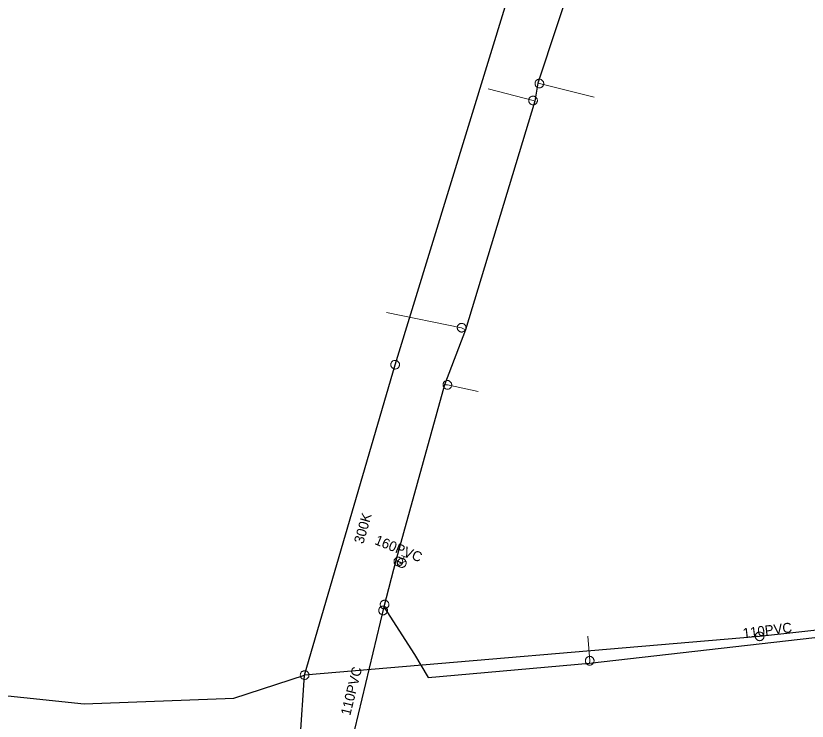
# Model space of a CAD drawing. Extents: x -741806 to -738704, y -1059275 to -1055387.
# Drawn here: x -740539.1 to -740459.3, y -1057576.9 to -1057505.9 of the extents above; entities that cross this region are included whole.
import ezdxf

# ---------------------------------------------------------------- set-up
doc = ezdxf.new("R2010")
doc.units = 0
doc.header["$LTSCALE"] = 0.4
for name, color, linetype, lineweight in [('2', 7, 'Continuous', 25), ('21', 7, 'Continuous', 13), ('3', 7, 'Continuous', 13), ('50', 7, 'Continuous', 13), ('51', 7, 'Continuous', 13), ('52', 7, 'Continuous', 25)]:
    doc.layers.add(name, color=color, linetype=linetype, lineweight=lineweight)
doc.layers.add('5', color=7, linetype='Continuous')
doc.layers.add('53', color=7, linetype='Continuous')

msp = doc.modelspace()

# ---------------------------------------------------------------- linework, layer by layer
at = {"layer": '2'}
msp.add_line((-740510.965, -1057587.065), (-740509.967, -1057572.304), dxfattribs=at)
for points in [[(-740509.967, -1057572.304), (-740500.848, -1057541.021), (-740485.947, -1057492.468), (-740470.69, -1057443.092), (-740463.206, -1057418.767)], [(-740283.166, -1057549.12), (-740314.092, -1057552.159), (-740363.478, -1057557.404), (-740409.581, -1057562.408), (-740464.129, -1057568.401), (-740509.967, -1057572.304)], [(-740633.142, -1057565.869), (-740616.157, -1057567.624), (-740600.686, -1057569.098), (-740568.695, -1057571.365), (-740532.184, -1057575.2), (-740517.113, -1057574.642), (-740509.967, -1057572.304)]]:
    msp.add_lwpolyline(points, dxfattribs=at)
at = {"layer": '21'}
for points in [[(-740486.488, -1057512.648), (-740486.32, -1057512.685), (-740480.791, -1057514.071)], [(-740486.78, -1057514.456), (-740486.956, -1057514.396), (-740491.467, -1057513.21)], [(-740493.754, -1057537.497), (-740494.153, -1057537.29), (-740501.713, -1057535.767)], [(-740495.864, -1057543.049), (-740495.588, -1057543.054), (-740492.478, -1057543.732)], [(-740481.265, -1057571.105), (-740481.25, -1057570.86), (-740481.438, -1057568.395)]]:
    msp.add_lwpolyline(points, dxfattribs=at)
at = {"layer": '3'}
for points in [[(-740500.724, -1057540.6), (-740500.769, -1057540.59), (-740500.814, -1057540.585), (-740500.86, -1057540.583), (-740500.905, -1057540.587), (-740500.95, -1057540.596), (-740500.995, -1057540.609), (-740501.036, -1057540.627), (-740501.077, -1057540.648), (-740501.114, -1057540.675), (-740501.149, -1057540.705), (-740501.18, -1057540.738), (-740501.209, -1057540.775), (-740501.231, -1057540.814), (-740501.252, -1057540.855), (-740501.267, -1057540.898), (-740501.278, -1057540.943), (-740501.282, -1057540.989), (-740501.284, -1057541.034), (-740501.28, -1057541.08), (-740501.271, -1057541.125), (-740501.258, -1057541.169), (-740501.241, -1057541.21), (-740501.218, -1057541.251), (-740501.193, -1057541.289), (-740501.162, -1057541.324), (-740501.129, -1057541.354), (-740501.093, -1057541.382), (-740501.053, -1057541.406), (-740501.012, -1057541.426), (-740500.968, -1057541.44), (-740500.925, -1057541.451), (-740500.879, -1057541.457), (-740500.833, -1057541.458), (-740500.787, -1057541.454), (-740500.743, -1057541.446), (-740500.698, -1057541.433), (-740500.657, -1057541.415), (-740500.616, -1057541.392), (-740500.579, -1057541.366), (-740500.544, -1057541.337), (-740500.513, -1057541.303), (-740500.484, -1057541.267), (-740500.461, -1057541.228), (-740500.441, -1057541.187), (-740500.427, -1057541.143), (-740500.416, -1057541.098), (-740500.41, -1057541.053), (-740500.409, -1057541.008), (-740500.413, -1057540.962), (-740500.422, -1057540.916), (-740500.435, -1057540.873), (-740500.452, -1057540.831), (-740500.475, -1057540.791), (-740500.5, -1057540.753), (-740500.531, -1057540.718), (-740500.564, -1057540.686), (-740500.6, -1057540.659), (-740500.64, -1057540.635), (-740500.681, -1057540.616)], [(-740509.843, -1057571.883), (-740509.888, -1057571.873), (-740509.933, -1057571.868), (-740509.979, -1057571.866), (-740510.024, -1057571.87), (-740510.069, -1057571.879), (-740510.114, -1057571.892), (-740510.155, -1057571.91), (-740510.196, -1057571.931), (-740510.233, -1057571.958), (-740510.268, -1057571.988), (-740510.299, -1057572.021), (-740510.328, -1057572.058), (-740510.35, -1057572.097), (-740510.371, -1057572.138), (-740510.386, -1057572.181), (-740510.397, -1057572.226), (-740510.401, -1057572.272), (-740510.403, -1057572.317), (-740510.399, -1057572.363), (-740510.39, -1057572.408), (-740510.377, -1057572.452), (-740510.36, -1057572.493), (-740510.337, -1057572.534), (-740510.312, -1057572.572), (-740510.281, -1057572.607), (-740510.248, -1057572.637), (-740510.212, -1057572.665), (-740510.172, -1057572.689), (-740510.131, -1057572.709), (-740510.087, -1057572.723), (-740510.044, -1057572.734), (-740509.998, -1057572.74), (-740509.952, -1057572.741), (-740509.906, -1057572.737), (-740509.862, -1057572.729), (-740509.817, -1057572.716), (-740509.776, -1057572.698), (-740509.735, -1057572.675), (-740509.698, -1057572.649), (-740509.663, -1057572.62), (-740509.632, -1057572.586), (-740509.603, -1057572.55), (-740509.58, -1057572.511), (-740509.56, -1057572.47), (-740509.546, -1057572.426), (-740509.535, -1057572.381), (-740509.529, -1057572.336), (-740509.528, -1057572.291), (-740509.532, -1057572.245), (-740509.541, -1057572.199), (-740509.554, -1057572.156), (-740509.571, -1057572.114), (-740509.594, -1057572.074), (-740509.619, -1057572.036), (-740509.65, -1057572.001), (-740509.683, -1057571.969), (-740509.719, -1057571.942), (-740509.759, -1057571.918), (-740509.8, -1057571.899)]]:
    msp.add_lwpolyline(points, close=True, dxfattribs=at)
msp.add_lwpolyline([(-740464.564, -1057568.448), (-740464.556, -1057568.492), (-740464.544, -1057568.536), (-740464.527, -1057568.58), (-740464.507, -1057568.62), (-740464.481, -1057568.658), (-740464.452, -1057568.694), (-740464.42, -1057568.726), (-740464.384, -1057568.755), (-740464.345, -1057568.779), (-740464.305, -1057568.8), (-740464.262, -1057568.816), (-740464.217, -1057568.828), (-740464.172, -1057568.834), (-740464.127, -1057568.837), (-740464.081, -1057568.834), (-740464.035, -1057568.827), (-740463.991, -1057568.815), (-740463.949, -1057568.799), (-740463.908, -1057568.777), (-740463.87, -1057568.752), (-740463.835, -1057568.723), (-740463.803, -1057568.691), (-740463.774, -1057568.655), (-740463.749, -1057568.617), (-740463.728, -1057568.575), (-740463.713, -1057568.532), (-740463.7, -1057568.489), (-740463.693, -1057568.443), (-740463.691, -1057568.397), (-740463.694, -1057568.351), (-740463.701, -1057568.307), (-740463.713, -1057568.263), (-740463.73, -1057568.219), (-740463.751, -1057568.178), (-740463.776, -1057568.141), (-740463.805, -1057568.105), (-740463.837, -1057568.073), (-740463.874, -1057568.044), (-740463.912, -1057568.02), (-740463.952, -1057567.999), (-740463.995, -1057567.983), (-740464.04, -1057567.971), (-740464.085, -1057567.964), (-740464.13, -1057567.962), (-740464.176, -1057567.965), (-740464.222, -1057567.972), (-740464.266, -1057567.984), (-740464.308, -1057568), (-740464.349, -1057568.022), (-740464.388, -1057568.047), (-740464.423, -1057568.076), (-740464.455, -1057568.108), (-740464.484, -1057568.144), (-740464.509, -1057568.182), (-740464.529, -1057568.224), (-740464.546, -1057568.267), (-740464.557, -1057568.31), (-740464.564, -1057568.356), (-740464.566, -1057568.402), (-740464.564, -1057568.447)], dxfattribs=at)
at = {"layer": '50'}
for p, q in [((-740500.211, -1057560.241), (-740499.925, -1057560.355)), ((-740500.018, -1057560.588), (-740499.925, -1057560.355)), ((-740499.64, -1057560.469), (-740499.925, -1057560.355)), ((-740500.183, -1057561.004), (-740500.595, -1057561.181)), ((-740500.183, -1057561.004), (-740499.775, -1057560.831))]:
    msp.add_line(p, q, dxfattribs=at)
msp.add_lwpolyline([(-740499.772, -1057561.172), (-740499.757, -1057561.125), (-740499.745, -1057561.081), (-740499.74, -1057561.033), (-740499.739, -1057560.987), (-740499.742, -1057560.943), (-740499.752, -1057560.895), (-740499.766, -1057560.852), (-740499.784, -1057560.807), (-740499.805, -1057560.766), (-740499.833, -1057560.729), (-740499.863, -1057560.693), (-740499.896, -1057560.66), (-740499.935, -1057560.633), (-740499.975, -1057560.609), (-740500.016, -1057560.589), (-740500.06, -1057560.575), (-740500.104, -1057560.563), (-740500.151, -1057560.558), (-740500.199, -1057560.557), (-740500.246, -1057560.561), (-740500.291, -1057560.57), (-740500.336, -1057560.583), (-740500.379, -1057560.601), (-740500.419, -1057560.623), (-740500.459, -1057560.65), (-740500.494, -1057560.68), (-740500.525, -1057560.714), (-740500.555, -1057560.752), (-740500.577, -1057560.793), (-740500.6, -1057560.833), (-740500.615, -1057560.879), (-740500.624, -1057560.924), (-740500.63, -1057560.968), (-740500.632, -1057561.017), (-740500.627, -1057561.063), (-740500.619, -1057561.109), (-740500.605, -1057561.153), (-740500.588, -1057561.197), (-740500.564, -1057561.239), (-740500.537, -1057561.276), (-740500.506, -1057561.312), (-740500.472, -1057561.343), (-740500.437, -1057561.372), (-740500.394, -1057561.397), (-740500.353, -1057561.417), (-740500.309, -1057561.432), (-740500.263, -1057561.441), (-740500.216, -1057561.448), (-740500.17, -1057561.449), (-740500.122, -1057561.445), (-740500.078, -1057561.436), (-740500.032, -1057561.423), (-740499.99, -1057561.405), (-740499.949, -1057561.383), (-740499.912, -1057561.354), (-740499.875, -1057561.326), (-740499.843, -1057561.291), (-740499.817, -1057561.253), (-740499.792, -1057561.214)], close=True, dxfattribs=at)
at = {"layer": '51'}
msp.add_lwpolyline([(-740485.893, -1057512.78), (-740485.885, -1057512.735), (-740485.882, -1057512.69), (-740485.884, -1057512.643), (-740485.891, -1057512.599), (-740485.902, -1057512.554), (-740485.918, -1057512.511), (-740485.939, -1057512.47), (-740485.963, -1057512.431), (-740485.992, -1057512.396), (-740486.024, -1057512.363), (-740486.06, -1057512.334), (-740486.098, -1057512.308), (-740486.138, -1057512.287), (-740486.181, -1057512.27), (-740486.225, -1057512.258), (-740486.27, -1057512.25), (-740486.316, -1057512.247), (-740486.361, -1057512.25), (-740486.407, -1057512.257), (-740486.452, -1057512.269), (-740486.494, -1057512.285), (-740486.535, -1057512.304), (-740486.574, -1057512.33), (-740486.61, -1057512.357), (-740486.642, -1057512.39), (-740486.672, -1057512.426), (-740486.697, -1057512.463), (-740486.718, -1057512.505), (-740486.735, -1057512.547), (-740486.747, -1057512.591), (-740486.754, -1057512.636), (-740486.757, -1057512.681), (-740486.755, -1057512.728), (-740486.749, -1057512.772), (-740486.737, -1057512.817), (-740486.721, -1057512.86), (-740486.7, -1057512.901), (-740486.676, -1057512.94), (-740486.647, -1057512.975), (-740486.615, -1057513.008), (-740486.58, -1057513.037), (-740486.542, -1057513.063), (-740486.501, -1057513.083), (-740486.459, -1057513.101), (-740486.414, -1057513.113), (-740486.369, -1057513.121), (-740486.323, -1057513.123), (-740486.278, -1057513.121), (-740486.232, -1057513.114), (-740486.188, -1057513.102), (-740486.145, -1057513.086), (-740486.104, -1057513.067), (-740486.066, -1057513.041), (-740486.03, -1057513.013), (-740485.997, -1057512.981), (-740485.968, -1057512.945), (-740485.943, -1057512.908), (-740485.921, -1057512.866), (-740485.905, -1057512.824)], close=True, dxfattribs=at)
for points in [[(-740487.369, -1057514.254), (-740487.382, -1057514.297), (-740487.389, -1057514.342), (-740487.393, -1057514.389), (-740487.391, -1057514.433), (-740487.384, -1057514.479), (-740487.373, -1057514.524), (-740487.357, -1057514.567), (-740487.338, -1057514.608), (-740487.312, -1057514.646), (-740487.285, -1057514.682), (-740487.253, -1057514.715), (-740487.217, -1057514.745), (-740487.18, -1057514.771), (-740487.139, -1057514.792), (-740487.096, -1057514.809), (-740487.052, -1057514.822), (-740487.007, -1057514.829), (-740486.962, -1057514.832), (-740486.916, -1057514.83), (-740486.87, -1057514.823), (-740486.826, -1057514.812), (-740486.783, -1057514.797), (-740486.742, -1057514.776), (-740486.703, -1057514.753), (-740486.667, -1057514.724), (-740486.634, -1057514.692), (-740486.605, -1057514.657), (-740486.579, -1057514.618), (-740486.558, -1057514.578), (-740486.54, -1057514.535), (-740486.529, -1057514.492), (-740486.521, -1057514.447), (-740486.518, -1057514.401), (-740486.519, -1057514.356), (-740486.526, -1057514.31), (-740486.537, -1057514.265), (-740486.553, -1057514.223), (-740486.573, -1057514.181), (-740486.598, -1057514.143), (-740486.626, -1057514.107), (-740486.658, -1057514.074), (-740486.693, -1057514.044), (-740486.731, -1057514.019), (-740486.771, -1057513.997), (-740486.814, -1057513.98), (-740486.858, -1057513.968), (-740486.903, -1057513.961), (-740486.949, -1057513.957), (-740486.995, -1057513.959), (-740487.04, -1057513.966), (-740487.084, -1057513.977), (-740487.127, -1057513.992), (-740487.168, -1057514.013), (-740487.207, -1057514.037), (-740487.243, -1057514.065), (-740487.277, -1057514.097), (-740487.305, -1057514.132), (-740487.331, -1057514.171), (-740487.352, -1057514.211), (-740487.369, -1057514.253)], [(-740493.716, -1057537.29), (-740493.718, -1057537.245), (-740493.725, -1057537.2), (-740493.737, -1057537.155), (-740493.753, -1057537.113), (-740493.774, -1057537.072), (-740493.799, -1057537.033), (-740493.828, -1057536.998), (-740493.86, -1057536.965), (-740493.896, -1057536.937), (-740493.934, -1057536.912), (-740493.975, -1057536.891), (-740494.018, -1057536.874), (-740494.062, -1057536.862), (-740494.107, -1057536.855), (-740494.153, -1057536.853), (-740494.199, -1057536.855), (-740494.244, -1057536.862), (-740494.288, -1057536.874), (-740494.331, -1057536.891), (-740494.372, -1057536.912), (-740494.41, -1057536.937), (-740494.446, -1057536.965), (-740494.478, -1057536.998), (-740494.507, -1057537.033), (-740494.532, -1057537.072), (-740494.553, -1057537.113), (-740494.569, -1057537.155), (-740494.581, -1057537.2), (-740494.588, -1057537.245), (-740494.591, -1057537.291), (-740494.588, -1057537.336), (-740494.581, -1057537.381), (-740494.569, -1057537.426), (-740494.553, -1057537.468), (-740494.532, -1057537.509), (-740494.507, -1057537.548), (-740494.478, -1057537.583), (-740494.446, -1057537.616), (-740494.41, -1057537.644), (-740494.372, -1057537.669), (-740494.331, -1057537.69), (-740494.288, -1057537.707), (-740494.244, -1057537.718), (-740494.199, -1057537.726), (-740494.153, -1057537.728), (-740494.107, -1057537.726), (-740494.062, -1057537.718), (-740494.018, -1057537.707), (-740493.975, -1057537.69), (-740493.934, -1057537.669), (-740493.896, -1057537.644), (-740493.86, -1057537.616), (-740493.828, -1057537.583), (-740493.799, -1057537.548), (-740493.774, -1057537.509), (-740493.753, -1057537.468), (-740493.737, -1057537.426), (-740493.725, -1057537.381), (-740493.718, -1057537.336), (-740493.716, -1057537.291)], [(-740495.151, -1057543.062), (-740495.152, -1057543.017), (-740495.158, -1057542.972), (-740495.169, -1057542.927), (-740495.184, -1057542.884), (-740495.205, -1057542.843), (-740495.229, -1057542.803), (-740495.257, -1057542.768), (-740495.289, -1057542.734), (-740495.324, -1057542.706), (-740495.362, -1057542.68), (-740495.402, -1057542.658), (-740495.445, -1057542.641), (-740495.489, -1057542.628), (-740495.534, -1057542.62), (-740495.58, -1057542.617), (-740495.626, -1057542.618), (-740495.671, -1057542.624), (-740495.715, -1057542.636), (-740495.758, -1057542.652), (-740495.8, -1057542.672), (-740495.838, -1057542.696), (-740495.875, -1057542.724), (-740495.907, -1057542.756), (-740495.937, -1057542.791), (-740495.962, -1057542.829), (-740495.984, -1057542.87), (-740496.001, -1057542.911), (-740496.014, -1057542.956), (-740496.022, -1057543.001), (-740496.025, -1057543.047), (-740496.023, -1057543.092), (-740496.017, -1057543.137), (-740496.006, -1057543.182), (-740495.991, -1057543.225), (-740495.97, -1057543.266), (-740495.946, -1057543.306), (-740495.918, -1057543.341), (-740495.886, -1057543.375), (-740495.851, -1057543.403), (-740495.813, -1057543.429), (-740495.773, -1057543.451), (-740495.73, -1057543.468), (-740495.686, -1057543.48), (-740495.641, -1057543.489), (-740495.595, -1057543.492), (-740495.549, -1057543.491), (-740495.504, -1057543.484), (-740495.46, -1057543.473), (-740495.417, -1057543.457), (-740495.375, -1057543.437), (-740495.337, -1057543.413), (-740495.3, -1057543.385), (-740495.268, -1057543.353), (-740495.238, -1057543.318), (-740495.213, -1057543.28), (-740495.191, -1057543.239), (-740495.174, -1057543.198), (-740495.161, -1057543.153), (-740495.153, -1057543.108), (-740495.151, -1057543.063)], [(-740500.118, -1057561.025), (-740500.103, -1057560.982), (-740500.093, -1057560.938), (-740500.087, -1057560.892), (-740500.087, -1057560.847), (-740500.091, -1057560.801), (-740500.1, -1057560.756), (-740500.114, -1057560.712), (-740500.131, -1057560.67), (-740500.154, -1057560.63), (-740500.18, -1057560.593), (-740500.21, -1057560.558), (-740500.244, -1057560.527), (-740500.28, -1057560.499), (-740500.32, -1057560.476), (-740500.362, -1057560.457), (-740500.405, -1057560.442), (-740500.449, -1057560.432), (-740500.495, -1057560.427), (-740500.541, -1057560.426), (-740500.587, -1057560.431), (-740500.631, -1057560.44), (-740500.675, -1057560.452), (-740500.717, -1057560.471), (-740500.757, -1057560.493), (-740500.795, -1057560.52), (-740500.83, -1057560.55), (-740500.86, -1057560.583), (-740500.888, -1057560.621), (-740500.911, -1057560.66), (-740500.931, -1057560.701), (-740500.945, -1057560.744), (-740500.955, -1057560.789), (-740500.96, -1057560.835), (-740500.961, -1057560.88), (-740500.957, -1057560.926), (-740500.948, -1057560.971), (-740500.934, -1057561.015), (-740500.917, -1057561.057), (-740500.894, -1057561.096), (-740500.868, -1057561.134), (-740500.837, -1057561.168), (-740500.804, -1057561.2), (-740500.767, -1057561.227), (-740500.728, -1057561.251), (-740500.686, -1057561.27), (-740500.643, -1057561.285), (-740500.598, -1057561.294), (-740500.553, -1057561.3), (-740500.507, -1057561.3), (-740500.461, -1057561.296), (-740500.416, -1057561.287), (-740500.372, -1057561.274), (-740500.331, -1057561.256), (-740500.291, -1057561.234), (-740500.253, -1057561.207), (-740500.218, -1057561.177), (-740500.188, -1057561.144), (-740500.16, -1057561.106), (-740500.137, -1057561.067), (-740500.118, -1057561.026)], [(-740501.624, -1057565.79), (-740501.625, -1057565.745), (-740501.633, -1057565.7), (-740501.645, -1057565.655), (-740501.661, -1057565.613), (-740501.682, -1057565.572), (-740501.706, -1057565.533), (-740501.736, -1057565.498), (-740501.768, -1057565.465), (-740501.804, -1057565.437), (-740501.842, -1057565.412), (-740501.883, -1057565.391), (-740501.926, -1057565.374), (-740501.97, -1057565.362), (-740502.015, -1057565.355), (-740502.061, -1057565.353), (-740502.107, -1057565.355), (-740502.152, -1057565.362), (-740502.196, -1057565.374), (-740502.239, -1057565.391), (-740502.28, -1057565.412), (-740502.318, -1057565.437), (-740502.353, -1057565.465), (-740502.386, -1057565.498), (-740502.415, -1057565.533), (-740502.44, -1057565.572), (-740502.461, -1057565.613), (-740502.477, -1057565.655), (-740502.489, -1057565.7), (-740502.496, -1057565.745), (-740502.499, -1057565.791), (-740502.496, -1057565.836), (-740502.489, -1057565.881), (-740502.477, -1057565.926), (-740502.461, -1057565.968), (-740502.44, -1057566.009), (-740502.415, -1057566.048), (-740502.386, -1057566.083), (-740502.353, -1057566.116), (-740502.318, -1057566.144), (-740502.28, -1057566.169), (-740502.239, -1057566.19), (-740502.196, -1057566.207), (-740502.152, -1057566.218), (-740502.107, -1057566.226), (-740502.061, -1057566.228), (-740502.015, -1057566.226), (-740501.97, -1057566.218), (-740501.926, -1057566.207), (-740501.883, -1057566.19), (-740501.842, -1057566.169), (-740501.804, -1057566.144), (-740501.768, -1057566.116), (-740501.736, -1057566.083), (-740501.706, -1057566.048), (-740501.682, -1057566.009), (-740501.661, -1057565.968), (-740501.645, -1057565.926), (-740501.633, -1057565.881), (-740501.625, -1057565.836), (-740501.624, -1057565.791)], [(-740502.024, -1057565.623), (-740501.98, -1057565.632), (-740501.935, -1057565.636), (-740501.888, -1057565.636), (-740501.844, -1057565.631), (-740501.799, -1057565.621), (-740501.755, -1057565.606), (-740501.714, -1057565.587), (-740501.674, -1057565.564), (-740501.638, -1057565.536), (-740501.604, -1057565.505), (-740501.574, -1057565.471), (-740501.546, -1057565.433), (-740501.524, -1057565.394), (-740501.506, -1057565.352), (-740501.493, -1057565.308), (-740501.483, -1057565.263), (-740501.479, -1057565.217), (-740501.479, -1057565.172), (-740501.485, -1057565.126), (-740501.495, -1057565.081), (-740501.51, -1057565.038), (-740501.528, -1057564.996), (-740501.552, -1057564.957), (-740501.579, -1057564.92), (-740501.611, -1057564.886), (-740501.645, -1057564.856), (-740501.682, -1057564.83), (-740501.723, -1057564.807), (-740501.764, -1057564.789), (-740501.808, -1057564.775), (-740501.853, -1057564.767), (-740501.898, -1057564.762), (-740501.945, -1057564.763), (-740501.989, -1057564.768), (-740502.034, -1057564.778), (-740502.078, -1057564.792), (-740502.119, -1057564.812), (-740502.159, -1057564.835), (-740502.195, -1057564.863), (-740502.229, -1057564.893), (-740502.259, -1057564.928), (-740502.286, -1057564.965), (-740502.308, -1057565.005), (-740502.327, -1057565.047), (-740502.34, -1057565.091), (-740502.35, -1057565.136), (-740502.353, -1057565.181), (-740502.353, -1057565.227), (-740502.348, -1057565.273), (-740502.337, -1057565.317), (-740502.323, -1057565.36), (-740502.304, -1057565.402), (-740502.28, -1057565.442), (-740502.254, -1057565.478), (-740502.222, -1057565.512), (-740502.188, -1057565.543), (-740502.151, -1057565.569), (-740502.11, -1057565.591), (-740502.068, -1057565.609), (-740502.025, -1057565.622)], [(-740480.813, -1057570.86), (-740480.815, -1057570.815), (-740480.822, -1057570.77), (-740480.834, -1057570.725), (-740480.85, -1057570.683), (-740480.871, -1057570.642), (-740480.896, -1057570.603), (-740480.925, -1057570.568), (-740480.957, -1057570.535), (-740480.993, -1057570.507), (-740481.031, -1057570.482), (-740481.072, -1057570.461), (-740481.115, -1057570.444), (-740481.159, -1057570.432), (-740481.204, -1057570.425), (-740481.25, -1057570.423), (-740481.296, -1057570.425), (-740481.341, -1057570.432), (-740481.385, -1057570.444), (-740481.428, -1057570.461), (-740481.469, -1057570.482), (-740481.507, -1057570.507), (-740481.543, -1057570.535), (-740481.575, -1057570.568), (-740481.604, -1057570.603), (-740481.629, -1057570.642), (-740481.65, -1057570.683), (-740481.666, -1057570.725), (-740481.678, -1057570.77), (-740481.685, -1057570.815), (-740481.688, -1057570.861), (-740481.685, -1057570.906), (-740481.678, -1057570.951), (-740481.666, -1057570.996), (-740481.65, -1057571.038), (-740481.629, -1057571.079), (-740481.604, -1057571.118), (-740481.575, -1057571.153), (-740481.543, -1057571.186), (-740481.507, -1057571.214), (-740481.469, -1057571.239), (-740481.428, -1057571.26), (-740481.385, -1057571.277), (-740481.341, -1057571.288), (-740481.296, -1057571.296), (-740481.25, -1057571.298), (-740481.204, -1057571.296), (-740481.159, -1057571.288), (-740481.115, -1057571.277), (-740481.072, -1057571.26), (-740481.031, -1057571.239), (-740480.993, -1057571.214), (-740480.957, -1057571.186), (-740480.925, -1057571.153), (-740480.896, -1057571.118), (-740480.871, -1057571.079), (-740480.85, -1057571.038), (-740480.834, -1057570.996), (-740480.822, -1057570.951), (-740480.815, -1057570.906), (-740480.813, -1057570.861)]]:
    msp.add_lwpolyline(points, dxfattribs=at)
at = {"layer": '52'}
msp.add_line((-740500.778, -1057560.762), (-740500.182, -1057561), dxfattribs=at)
for points in [[(-740407.857, -1057263.098), (-740439.467, -1057360.607), (-740447.059, -1057384.081), (-740447.248, -1057384.679), (-740452.412, -1057401.031), (-740457.603, -1057418.83), (-740467.015, -1057450.047), (-740468.397, -1057454.838), (-740469.89, -1057459.936), (-740472.616, -1057468.997), (-740478.407, -1057487.088), (-740480.659, -1057495.081), (-740486.488, -1057512.648), (-740486.78, -1057514.456), (-740493.754, -1057537.497), (-740495.864, -1057543.049), (-740500.778, -1057560.762), (-740501.975, -1057565.431)], [(-740501.975, -1057565.431), (-740498.884, -1057570.244), (-740497.519, -1057572.537), (-740481.265, -1057571.105), (-740444.131, -1057566.855), (-740420.085, -1057564.335), (-740405.726, -1057562.816), (-740391.932, -1057561.267), (-740379.41, -1057560.259), (-740347.938, -1057556.495), (-740327.93, -1057554.585), (-740327.193, -1057554.446), (-740306.52, -1057552.313), (-740284.403, -1057550.291), (-740281.57, -1057549.571)], [(-740501.975, -1057565.431), (-740506.805, -1057585.527), (-740505.035, -1057602.584), (-740503.752, -1057611.588), (-740503.249, -1057612.745)]]:
    msp.add_lwpolyline(points, dxfattribs=at)

# ---------------------------------------------------------------- texts
at = {"layer": '5'}
msp.add_text('300K', height=1, rotation=74, dxfattribs=at).set_placement((-740504.06, -1057559.138))
at = {"layer": '53'}
for s, rotation, p in [('160PVC', 338, (-740502.993, -1057559.084)), ('110PVC', 7, (-740465.762, -1057568.59)), ('110PVC', 76, (-740505.377, -1057576.445))]:
    msp.add_text(s, height=1, rotation=rotation, dxfattribs=at).set_placement(p)

doc.saveas('drawing.dxf')
